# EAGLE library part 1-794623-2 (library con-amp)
MICRO MATE N LOK Dual Row, grid 1.5 mm Source: http://catalog.tycoelectronics.com .. ENG_CD_794623_F.pdf
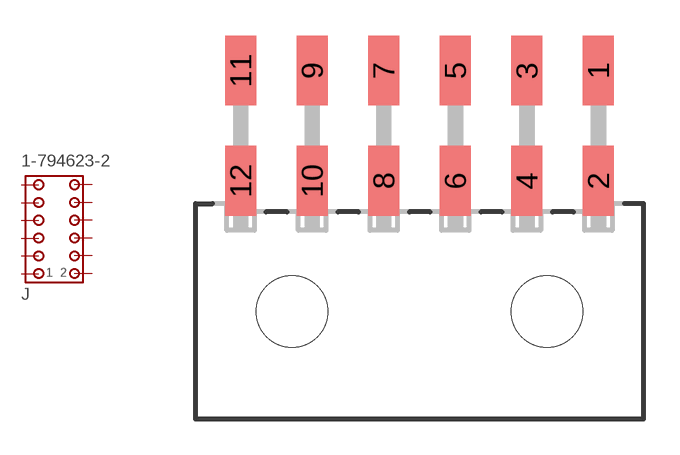
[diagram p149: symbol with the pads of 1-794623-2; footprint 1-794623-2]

Designator prefix J

## 1-794623-2 (MF: TYCO ELECTRONICS; MPN: 1-794623-2; OC_FARNELL: unknown; OC_NEWARK: 10H3683)  [1-794623-2]
1  1  pas
2  2  pas
3  3  pas
4  4  pas
5  5  pas
6  6  pas
7  7  pas
8  8  pas
9  9  pas
10  10  pas
11  11  pas
12  12  pas

## Footprint 1-794623-2 (pad centres in mm)
MICRO MATE N LOK Dual Row, grid 1.5 mm Source: http://catalog.tycoelectronics.com .. ENG_CD_794623_F.pdf
smd 1.3 x 2.92: 1 7.5,10.1; 2 7.5,5.48; 3 4.5,10.1; 4 4.5,5.48; 5 1.5,10.1; 6 1.5,5.48; 7 -1.5,10.1; 8 -1.5,5.48; 9 -4.5,10.1; 10 -4.5,5.48; 11 -7.5,10.1; 12 -7.5,5.48
hole 3 at -5.35,0
hole 3 at 5.35,0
